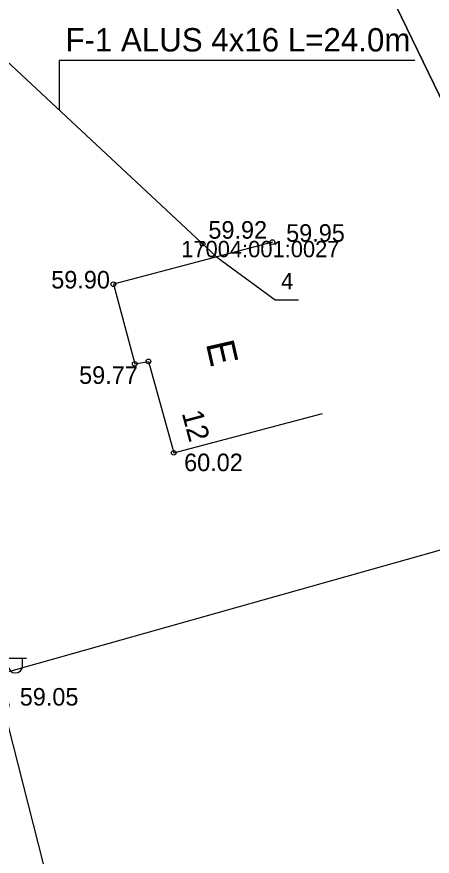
# Model space of a CAD drawing. Extents: x 643307 to 644029, y 6457938 to 6458417.
# Drawn here: x 643522.41 to 643540.18, y 6458210.53 to 6458246.45 of the extents above; entities that cross this region are included whole.
import ezdxf

# ---------------------------------------------------------------- set-up
doc = ezdxf.new("R2010")
doc.units = 0
for name, color, linetype in [('11_KTRASS', 7, 'Continuous'), ('14_MPOHULIIN', 7, 'Continuous'), ('1_HOONE', 7, 'Continuous'), ('26_POST', 7, 'Continuous'), ('40_PIIR', 7, 'Continuous'), ('59_KORGUS', 7, 'Continuous'), ('62_MOOTMPUNKT', 7, 'Continuous'), ('Level 25', 7, 'Continuous'), ('Level 55', 7, 'Continuous')]:
    doc.layers.add(name, color=color, linetype=linetype)

# ---------------------------------------------------------------- blocks, each defined once
blk = doc.blocks.new('VAPOST')
at = {"layer": '11_KTRASS'}
for p, q in [((0, 0.5), (0, 4.5)), ((0, 4), (2, 4)), ((0.453, 3.358), (0.453, 4)), ((1.679, 3.358), (1.679, 4)), ((0, 0), (0, 0))]:
    blk.add_line(p, q, dxfattribs=at)
for radius in [0.5, 0.254]:
    blk.add_circle((0, 0), radius, dxfattribs=at)
blk.add_arc((1.066, 3.358), 0.613, 180, 0, dxfattribs=at)
blk = doc.blocks.new('RING02')
at = {"layer": '59_KORGUS'}
blk.add_circle((0, 0), 0.2, dxfattribs=at)

msp = doc.modelspace()

# ---------------------------------------------------------------- linework, layer by layer
at = {"layer": '14_MPOHULIIN'}
for points in [[(643513.386, 6458252.587), (643522.173, 6458244.382), (643530.959, 6458236.177)], [(643521.823, 6458217), (643527.652, 6458194.051)], [(643521.823, 6458217), (643527.652, 6458194.051)]]:
    msp.add_lwpolyline(points, dxfattribs=at)
at = {"layer": '1_HOONE'}
msp.add_lwpolyline([(643533.346, 6458236.809), (643526.548, 6458235.007), (643527.457, 6458231.6), (643528.044, 6458231.704), (643529.125, 6458227.793), (643535.493, 6458229.48)], dxfattribs=at)
at = {"layer": '40_PIIR'}
for points in [[(643548.78, 6458225.97), (643571.28, 6458236.85), (643555.6, 6458269.25), (643533.09, 6458258.36)], [(643521.24, 6458218.21), (643548.78, 6458225.97), (643533.09, 6458258.36), (643512.36, 6458253.09)]]:
    msp.add_lwpolyline(points, close=True, dxfattribs=at)
at = {"layer": 'Level 25'}
for points in [[(643539.432, 6458244.583), (643524.232, 6458244.583), (643524.232, 6458242.49)], [(643530.959, 6458236.177), (643533.455, 6458234.341), (643534.455, 6458234.341)]]:
    msp.add_lwpolyline(points, dxfattribs=at)
at = {"layer": 'Level 55'}
for p, q in [((643533.346, 6458236.809), (643533.346, 6458236.809)), ((643530.359, 6458236.738), (643530.359, 6458236.738)), ((643526.548, 6458235.007), (643526.548, 6458235.007)), ((643527.457, 6458231.6), (643527.457, 6458231.6)), ((643528.044, 6458231.704), (643528.044, 6458231.704)), ((643529.125, 6458227.793), (643529.125, 6458227.793))]:
    msp.add_line(p, q, dxfattribs=at)

# ---------------------------------------------------------------- block references
at = {"layer": '26_POST', "xscale": 0.5, "yscale": 0.5}
msp.add_blockref('VAPOST', (643521.823, 6458217), dxfattribs=at)
at = {"layer": '62_MOOTMPUNKT', "xscale": 0.5, "yscale": 0.5}
for p in [(643530.359, 6458236.738), (643533.346, 6458236.809), (643526.548, 6458235.007), (643528.044, 6458231.704), (643527.457, 6458231.6), (643529.125, 6458227.793)]:
    msp.add_blockref('RING02', p, dxfattribs=at)

# ---------------------------------------------------------------- texts
at = {"layer": '1_HOONE'}
for s, height, rotation, p in [('E', 1.2, 282.8554, (643530.494, 6458232.466)), ('12', 0.9, 284.9667, (643529.463, 6458229.493))]:
    msp.add_text(s, height=height, rotation=rotation, dxfattribs=at).set_placement(p)
at = {"layer": '40_PIIR'}
msp.add_text('17004:001:0027', height=0.7, dxfattribs=at).set_placement((643529.444, 6458236.162))
at = {"layer": '59_KORGUS'}
for s, p in [('59.92', (643530.606, 6458236.956)), ('59.95', (643533.931, 6458236.824)), ('59.90', (643523.886, 6458234.826)), ('59.77', (643525.078, 6458230.745)), ('60.02', (643529.568, 6458227.009)), ('59.05', (643522.54, 6458216.977))]:
    msp.add_text(s, height=0.75, dxfattribs=at).set_placement(p)
at = {"layer": 'Level 25'}
for s, height, p in [('F-1 ALUS 4x16 L=24.0m', 1, (643524.49, 6458244.967)), (' 4', 0.7, (643533.455, 6458234.791))]:
    msp.add_text(s, height=height, dxfattribs=at).set_placement(p)

doc.saveas('drawing.dxf')
